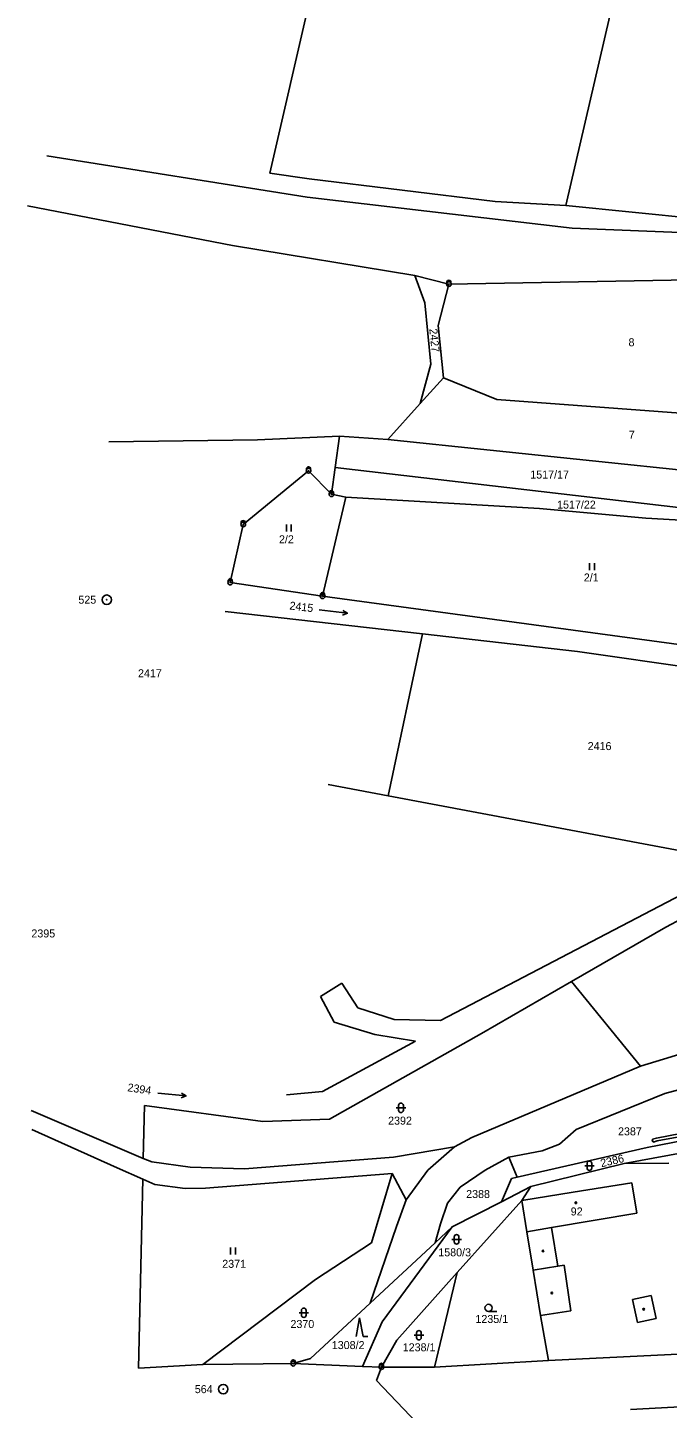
# Model space of a CAD drawing. Extents: x -801826 to -800592, y -1032871 to -1031813.
# Drawn here: x -801825.6 to -801689.7, y -1032516 to -1032222.7 of the extents above; entities that cross this region are included whole.
import ezdxf

# ---------------------------------------------------------------- set-up
doc = ezdxf.new("R2010")
doc.units = 0
for name, color, linetype in [('Vrstva 1', 7, 'Continuous'), ('Vrstva 17', 7, 'Continuous'), ('Vrstva 18', 7, 'Continuous'), ('Vrstva 19', 7, 'Continuous'), ('Vrstva 24', 7, 'Continuous'), ('Vrstva 25', 7, 'Continuous'), ('Vrstva 27', 7, 'Continuous'), ('Vrstva 4', 7, 'Continuous')]:
    doc.layers.add(name, color=color, linetype=linetype)

msp = doc.modelspace()

# ---------------------------------------------------------------- linework, layer by layer
at = {"layer": 'Vrstva 1'}
for p, q in [((-801735.27, -1032084.52), (-801774.16, -1032253.56)), ((-801673.2, -1032095.09), (-801711.24, -1032260.47)), ((-801821.55, -1032249.9), (-801766.23, -1032258.67)), ((-801765.81, -1032254.79), (-801774.16, -1032253.56)), ((-801726.32, -1032259.58), (-801765.81, -1032254.79)), ((-801825.6, -1032260.53), (-801782.08, -1032268.91)), ((-801766.23, -1032258.67), (-801709.92, -1032265.27)), ((-801711.24, -1032260.47), (-801726.32, -1032259.58)), ((-801678.99, -1032263.72), (-801711.24, -1032260.47)), ((-801709.92, -1032265.27), (-801683.45, -1032266.31)), ((-801782.08, -1032268.91), (-801743.35, -1032275.3)), ((-801743.35, -1032275.3), (-801741.22, -1032281.09)), ((-801743.35, -1032275.3), (-801736.12, -1032277.15)), ((-801736.12, -1032277.15), (-801738.4, -1032285.91)), ((-801684.96, -1032276.24), (-801736.12, -1032277.15)), ((-801741.22, -1032281.09), (-801739.96, -1032294.18)), ((-801738.4, -1032285.91), (-801737.24, -1032297.03)), ((-801739.96, -1032294.18), (-801742.19, -1032302.53)), ((-801737.24, -1032297.03), (-801742.19, -1032302.53)), ((-801737.24, -1032297.03), (-801725.9, -1032301.68)), ((-801742.19, -1032302.53), (-801749.06, -1032310.16)), ((-801725.9, -1032301.68), (-801670.45, -1032305.78)), ((-801776.77, -1032310.24), (-801808.32, -1032310.62)), ((-801759.34, -1032309.48), (-801776.77, -1032310.24)), ((-801759.34, -1032309.48), (-801760.27, -1032316.11)), ((-801749.06, -1032310.16), (-801759.34, -1032309.48)), ((-801683.9, -1032316.94), (-801749.06, -1032310.16)), ((-801760.27, -1032316.11), (-801761.07, -1032321.79)), ((-801677.59, -1032325.75), (-801760.27, -1032316.11)), ((-801765.92, -1032316.78), (-801779.81, -1032328.19)), ((-801761.07, -1032321.79), (-801765.92, -1032316.78)), ((-801758.02, -1032322.38), (-801761.07, -1032321.79)), ((-801758.02, -1032322.38), (-801762.93, -1032343.47)), ((-801716.9, -1032324.83), (-801758.02, -1032322.38)), ((-801694.3, -1032326.88), (-801716.9, -1032324.83)), ((-801675.63, -1032327.96), (-801694.3, -1032326.88)), ((-801779.81, -1032328.19), (-801782.56, -1032340.54)), ((-801782.56, -1032340.54), (-801762.93, -1032343.47)), ((-801762.93, -1032343.47), (-801669.64, -1032356.14)), ((-801783.63, -1032346.67), (-801741.72, -1032351.46)), ((-801749.03, -1032385.85), (-801741.72, -1032351.46)), ((-801741.72, -1032351.46), (-801708.77, -1032355.22)), ((-801708.77, -1032355.22), (-801678.47, -1032359.53)), ((-801749.03, -1032385.85), (-801761.73, -1032383.46)), ((-801667.77, -1032401.12), (-801749.03, -1032385.85)), ((-801686.67, -1032406.79), (-801737.87, -1032433.62)), ((-801690.04, -1032413.74), (-801680.62, -1032408.73)), ((-801710.06, -1032425.3), (-801690.04, -1032413.74)), ((-801758.84, -1032425.63), (-801763.4, -1032428.49)), ((-801755.48, -1032430.87), (-801758.84, -1032425.63)), ((-801729.16, -1032436.33), (-801710.06, -1032425.3)), ((-801710.06, -1032425.3), (-801695.4, -1032443.28)), ((-801763.4, -1032428.49), (-801760.51, -1032433.91)), ((-801747.71, -1032433.41), (-801755.48, -1032430.87)), ((-801737.87, -1032433.62), (-801747.71, -1032433.41)), ((-801761.48, -1032454.58), (-801729.16, -1032436.33)), ((-801760.51, -1032433.91), (-801751.87, -1032436.57)), ((-801695.4, -1032443.28), (-801670.63, -1032435.77)), ((-801743.23, -1032437.99), (-801762.94, -1032448.64)), ((-801751.87, -1032436.57), (-801743.23, -1032437.99)), ((-801695.4, -1032443.28), (-801731.27, -1032458.45)), ((-801690.26, -1032449.08), (-801675.62, -1032445.2)), ((-801762.94, -1032448.64), (-801770.63, -1032449.38)), ((-801709.05, -1032456.76), (-801690.26, -1032449.08)), ((-801801.04, -1032462.88), (-801824.88, -1032452.73)), ((-801800.8, -1032451.65), (-801801.04, -1032462.88)), ((-801800.8, -1032451.65), (-801775.63, -1032455.03)), ((-801824.72, -1032456.76), (-801806.6, -1032464.86)), ((-801775.63, -1032455.03), (-801761.48, -1032454.58)), ((-801712.59, -1032459.86), (-801709.05, -1032456.76)), ((-801674.04, -1032456.69), (-801693.97, -1032460.57)), ((-801731.27, -1032458.45), (-801734.94, -1032460.43)), ((-801716.27, -1032461.26), (-801712.59, -1032459.86)), ((-801799.25, -1032463.64), (-801801.04, -1032462.88)), ((-801747.91, -1032462.6), (-801779.52, -1032465.11)), ((-801734.94, -1032460.43), (-801747.91, -1032462.6)), ((-801740.57, -1032465.41), (-801734.94, -1032460.43)), ((-801728.39, -1032465.4), (-801723.37, -1032462.61)), ((-801723.37, -1032462.61), (-801716.27, -1032461.26)), ((-801721.64, -1032466.9), (-801723.37, -1032462.61)), ((-801693.97, -1032460.57), (-801721.64, -1032466.9)), ((-801679.19, -1032460.32), (-801698.85, -1032463.99)), ((-801806.6, -1032464.86), (-801801.14, -1032467.3)), ((-801791.07, -1032464.76), (-801799.25, -1032463.64)), ((-801779.52, -1032465.11), (-801791.07, -1032464.76)), ((-801745.16, -1032471.69), (-801740.57, -1032465.41)), ((-801733.69, -1032469), (-801728.39, -1032465.4)), ((-801698.85, -1032463.99), (-801718.69, -1032468.86)), ((-801689.37, -1032463.87), (-801698.85, -1032463.99)), ((-801802.03, -1032507.45), (-801801.14, -1032467.3)), ((-801801.14, -1032467.3), (-801798.59, -1032468.44)), ((-801798.59, -1032468.44), (-801792.1, -1032469.3)), ((-801787.81, -1032469.18), (-801748.18, -1032466.07)), ((-801748.18, -1032466.07), (-801752.54, -1032480.82)), ((-801748.18, -1032466.07), (-801745.16, -1032471.69)), ((-801724.95, -1032472.08), (-801722.79, -1032467.16)), ((-801722.79, -1032467.16), (-801721.64, -1032466.9)), ((-801792.1, -1032469.3), (-801787.81, -1032469.18)), ((-801745.16, -1032471.69), (-801747.27, -1032477.37)), ((-801736.43, -1032472.41), (-801733.69, -1032469)), ((-801718.69, -1032468.86), (-801724.95, -1032472.08)), ((-801720.65, -1032471.84), (-801718.69, -1032468.86)), ((-801737.93, -1032476.78), (-801736.43, -1032472.41)), ((-801724.95, -1032472.08), (-801735.39, -1032477.45)), ((-801734.33, -1032487.15), (-801720.65, -1032471.84)), ((-801720.65, -1032471.84), (-801719.57, -1032478.45)), ((-801747.27, -1032477.37), (-801752.87, -1032493.66)), ((-801750.27, -1032497.6), (-801735.39, -1032477.45)), ((-801739, -1032480.8), (-801737.93, -1032476.78)), ((-801735.39, -1032477.45), (-801739, -1032480.8)), ((-801719.57, -1032478.45), (-801718.23, -1032486.64)), ((-801752.54, -1032480.82), (-801764.45, -1032488.62)), ((-801739, -1032480.8), (-801752.87, -1032493.66)), ((-801764.45, -1032488.62), (-801788.41, -1032506.68)), ((-801747.16, -1032501.52), (-801734.33, -1032487.15)), ((-801739.19, -1032507.22), (-801734.33, -1032487.15)), ((-801718.23, -1032486.64), (-801716.65, -1032496.28)), ((-801752.87, -1032493.66), (-801765.49, -1032505.36)), ((-801754.44, -1032507.07), (-801750.27, -1032497.6)), ((-801716.65, -1032496.28), (-801714.97, -1032505.84)), ((-801750.46, -1032507.23), (-801747.16, -1032501.52)), ((-801714.97, -1032505.84), (-801665.64, -1032503.36)), ((-801788.41, -1032506.68), (-801802.03, -1032507.45)), ((-801769.17, -1032506.49), (-801788.41, -1032506.68)), ((-801765.49, -1032505.36), (-801769.17, -1032506.49)), ((-801769.17, -1032506.49), (-801754.44, -1032507.07)), ((-801714.97, -1032505.84), (-801739.19, -1032507.22)), ((-801754.44, -1032507.07), (-801750.46, -1032507.23)), ((-801750.46, -1032507.23), (-801751.51, -1032510.07)), ((-801739.19, -1032507.22), (-801750.46, -1032507.23)), ((-801751.51, -1032510.07), (-801742.91, -1032519.09)), ((-801697.53, -1032516.2), (-801650.95, -1032513.86))]:
    msp.add_line(p, q, dxfattribs=at)
at = {"layer": 'Vrstva 24'}
for centre, radius in [((-801736.12, -1032277.15), 0.5), ((-801736.12, -1032277.15), 0.0364), ((-801765.92, -1032316.78), 0.5), ((-801765.92, -1032316.78), 0.0364), ((-801761.07, -1032321.79), 0.5), ((-801761.07, -1032321.79), 0.0364), ((-801779.81, -1032328.19), 0.5), ((-801779.81, -1032328.19), 0.0364), ((-801782.56, -1032340.54), 0.5), ((-801782.56, -1032340.54), 0.0364), ((-801808.78, -1032344.19), 1), ((-801808.78, -1032344.19), 0.0439), ((-801762.93, -1032343.47), 0.5), ((-801762.93, -1032343.47), 0.0364), ((-801769.17, -1032506.49), 0.5), ((-801769.17, -1032506.49), 0.0364), ((-801750.46, -1032507.23), 0.5), ((-801750.46, -1032507.23), 0.0364), ((-801784.05, -1032511.9), 1), ((-801784.05, -1032511.9), 0.0439)]:
    msp.add_circle(centre, radius, dxfattribs=at)
for centre in [(-801736.12, -1032276.78), (-801765.92, -1032316.41), (-801761.07, -1032321.42), (-801779.81, -1032327.82), (-801782.56, -1032340.17), (-801762.93, -1032343.1), (-801769.17, -1032506.12), (-801750.46, -1032506.86)]:
    msp.add_arc(centre, 0.45, 344.4473, 196.3778, dxfattribs=at)
at = {"layer": 'Vrstva 25'}
for p, q in [((-801770.63, -1032328.21), (-801770.63, -1032329.71)), ((-801769.6, -1032329.71), (-801769.6, -1032328.21)), ((-801706.22, -1032336.42), (-801706.22, -1032337.92)), ((-801705.2, -1032337.92), (-801705.2, -1032336.42)), ((-801763.64, -1032346.38), (-801757.68, -1032347.08)), ((-801797.93, -1032449.04), (-801791.95, -1032449.62)), ((-801747.29, -1032452.14), (-801745.29, -1032452.14)), ((-801746.79, -1032452.64), (-801746.79, -1032451.64)), ((-801745.79, -1032452.64), (-801745.79, -1032451.64)), ((-801707.27, -1032464.44), (-801705.27, -1032464.44)), ((-801706.77, -1032464.94), (-801706.77, -1032463.94)), ((-801705.77, -1032464.94), (-801705.77, -1032463.94)), ((-801735.47, -1032480.08), (-801733.47, -1032480.08)), ((-801734.97, -1032480.58), (-801734.97, -1032479.58)), ((-801733.97, -1032480.58), (-801733.97, -1032479.58)), ((-801782.49, -1032481.8), (-801782.49, -1032483.3)), ((-801781.46, -1032483.3), (-801781.46, -1032481.8)), ((-801767.44, -1032496.17), (-801767.44, -1032495.17)), ((-801766.44, -1032496.17), (-801766.44, -1032495.17)), ((-801767.94, -1032495.67), (-801765.94, -1032495.67)), ((-801755.08, -1032496.72), (-801755.82, -1032500.72)), ((-801755.08, -1032496.72), (-801754.35, -1032500.72)), ((-801725.95, -1032495.38), (-801727.7, -1032495.38)), ((-801754.35, -1032500.72), (-801753.35, -1032500.72)), ((-801743.47, -1032500.46), (-801741.47, -1032500.46)), ((-801742.97, -1032500.96), (-801742.97, -1032499.96)), ((-801741.97, -1032500.96), (-801741.97, -1032499.96))]:
    msp.add_line(p, q, dxfattribs=at)
for points in [[(-801758.61, -1032346.47), (-801757.68, -1032347.08), (-801758.73, -1032347.46)], [(-801792.9, -1032449.02), (-801791.95, -1032449.62), (-801793, -1032450.02)]]:
    msp.add_lwpolyline(points, dxfattribs=at)
for centre, radius in [((-801709.15, -1032472.31), 0.175), ((-801716.13, -1032482.54), 0.175), ((-801714.25, -1032491.47), 0.175), ((-801727.7, -1032494.63), 0.75), ((-801694.75, -1032494.92), 0.175)]:
    msp.add_circle(centre, radius, dxfattribs=at)
for centre, start, end in [((-801746.29, -1032451.64), 0, 180), ((-801746.29, -1032452.64), 180, 0), ((-801706.27, -1032463.94), 0, 180), ((-801706.27, -1032464.94), 180, 0), ((-801734.47, -1032479.58), 0, 180), ((-801734.47, -1032480.58), 180, 0), ((-801766.94, -1032495.17), 0, 180), ((-801766.94, -1032496.17), 180, 0), ((-801742.47, -1032499.96), 0, 180), ((-801742.47, -1032500.96), 180, 0)]:
    msp.add_arc(centre, 0.5, start, end, dxfattribs=at)
at = {"layer": 'Vrstva 27'}
msp.add_lwpolyline([(-801674.23, -1032455.3), (-801674.15, -1032455.9), (-801680.4, -1032457.11), (-801686.82, -1032458.22), (-801691.87, -1032459.13), (-801692.68, -1032459.41), (-801692.73, -1032459.24), (-801692.87, -1032459.28), (-801692.95, -1032458.98), (-801692.82, -1032458.95), (-801692.86, -1032458.83), (-801692.03, -1032458.55), (-801686.92, -1032457.62), (-801680.5, -1032456.51), (-801674.23, -1032455.3)], dxfattribs=at)
at = {"layer": 'Vrstva 4'}
for p, q in [((-801697.28, -1032468.06), (-801709.73, -1032470.08)), ((-801696.22, -1032474.54), (-801697.28, -1032468.06)), ((-801709.73, -1032470.08), (-801720.65, -1032471.84)), ((-801714.31, -1032477.59), (-801696.22, -1032474.54)), ((-801714.31, -1032477.59), (-801719.57, -1032478.45)), ((-801712.95, -1032485.78), (-801714.31, -1032477.59)), ((-801712.95, -1032485.78), (-801718.23, -1032486.64)), ((-801711.62, -1032485.56), (-801712.95, -1032485.78)), ((-801710.23, -1032495.26), (-801711.62, -1032485.56)), ((-801697.12, -1032492.86), (-801693.14, -1032492)), ((-801693.14, -1032492), (-801692.08, -1032496.89)), ((-801697.12, -1032492.86), (-801696.06, -1032497.75)), ((-801716.65, -1032496.28), (-801710.23, -1032495.26)), ((-801692.08, -1032496.89), (-801696.06, -1032497.75))]:
    msp.add_line(p, q, dxfattribs=at)

# ---------------------------------------------------------------- texts
at = {"layer": 'Vrstva 17'}
for s, p in [('525', (-801814.82, -1032345.04)), ('564', (-801790.09, -1032512.75))]:
    msp.add_text(s, height=1.7, dxfattribs=at).set_placement(p)
at = {"layer": 'Vrstva 18'}
for s, rotation, p in [('2427', 275.8219, (-801740.28, -1032286.68)), ('2415', 353.2285, (-801770.05, -1032346.25)), ('2394', 351.6242, (-801804.48, -1032448.6)), ('2386', 13.0062, (-801703.71, -1032464.77))]:
    msp.add_text(s, height=1.7, rotation=rotation, dxfattribs=at).set_placement(p)
for s, p in [('8', (-801697.96, -1032290.35)), ('7', (-801697.9, -1032310.01)), ('1517/17', (-801718.83, -1032318.46)), ('1517/22', (-801713.13, -1032324.84)), ('2/2', (-801772.21, -1032332.21)), ('2/1', (-801707.46, -1032340.32)), ('2417', (-801802.15, -1032360.66)), ('2416', (-801706.64, -1032376.14)), ('2395', (-801824.8, -1032415.94)), ('2392', (-801749.03, -1032455.71)), ('2387', (-801700.19, -1032457.99)), ('2388', (-801732.45, -1032471.3)), ('1580/3', (-801738.37, -1032483.69)), ('2371', (-801784.26, -1032486.13)), ('2370', (-801769.77, -1032498.92)), ('1235/1', (-801730.48, -1032497.84)), ('1308/2', (-801760.99, -1032503.39)), ('1238/1', (-801745.92, -1032503.86))]:
    msp.add_text(s, height=1.7, dxfattribs=at).set_placement(p)
at = {"layer": 'Vrstva 19'}
msp.add_text('92', height=1.7, dxfattribs=at).set_placement((-801710.24, -1032475))

doc.saveas('drawing.dxf')
